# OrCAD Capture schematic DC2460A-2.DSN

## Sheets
1 LTC5566 - PAGE2: size Custom; title: DUAL PROGRAMMABLE GAIN MIXER; rev: 2; company: TM
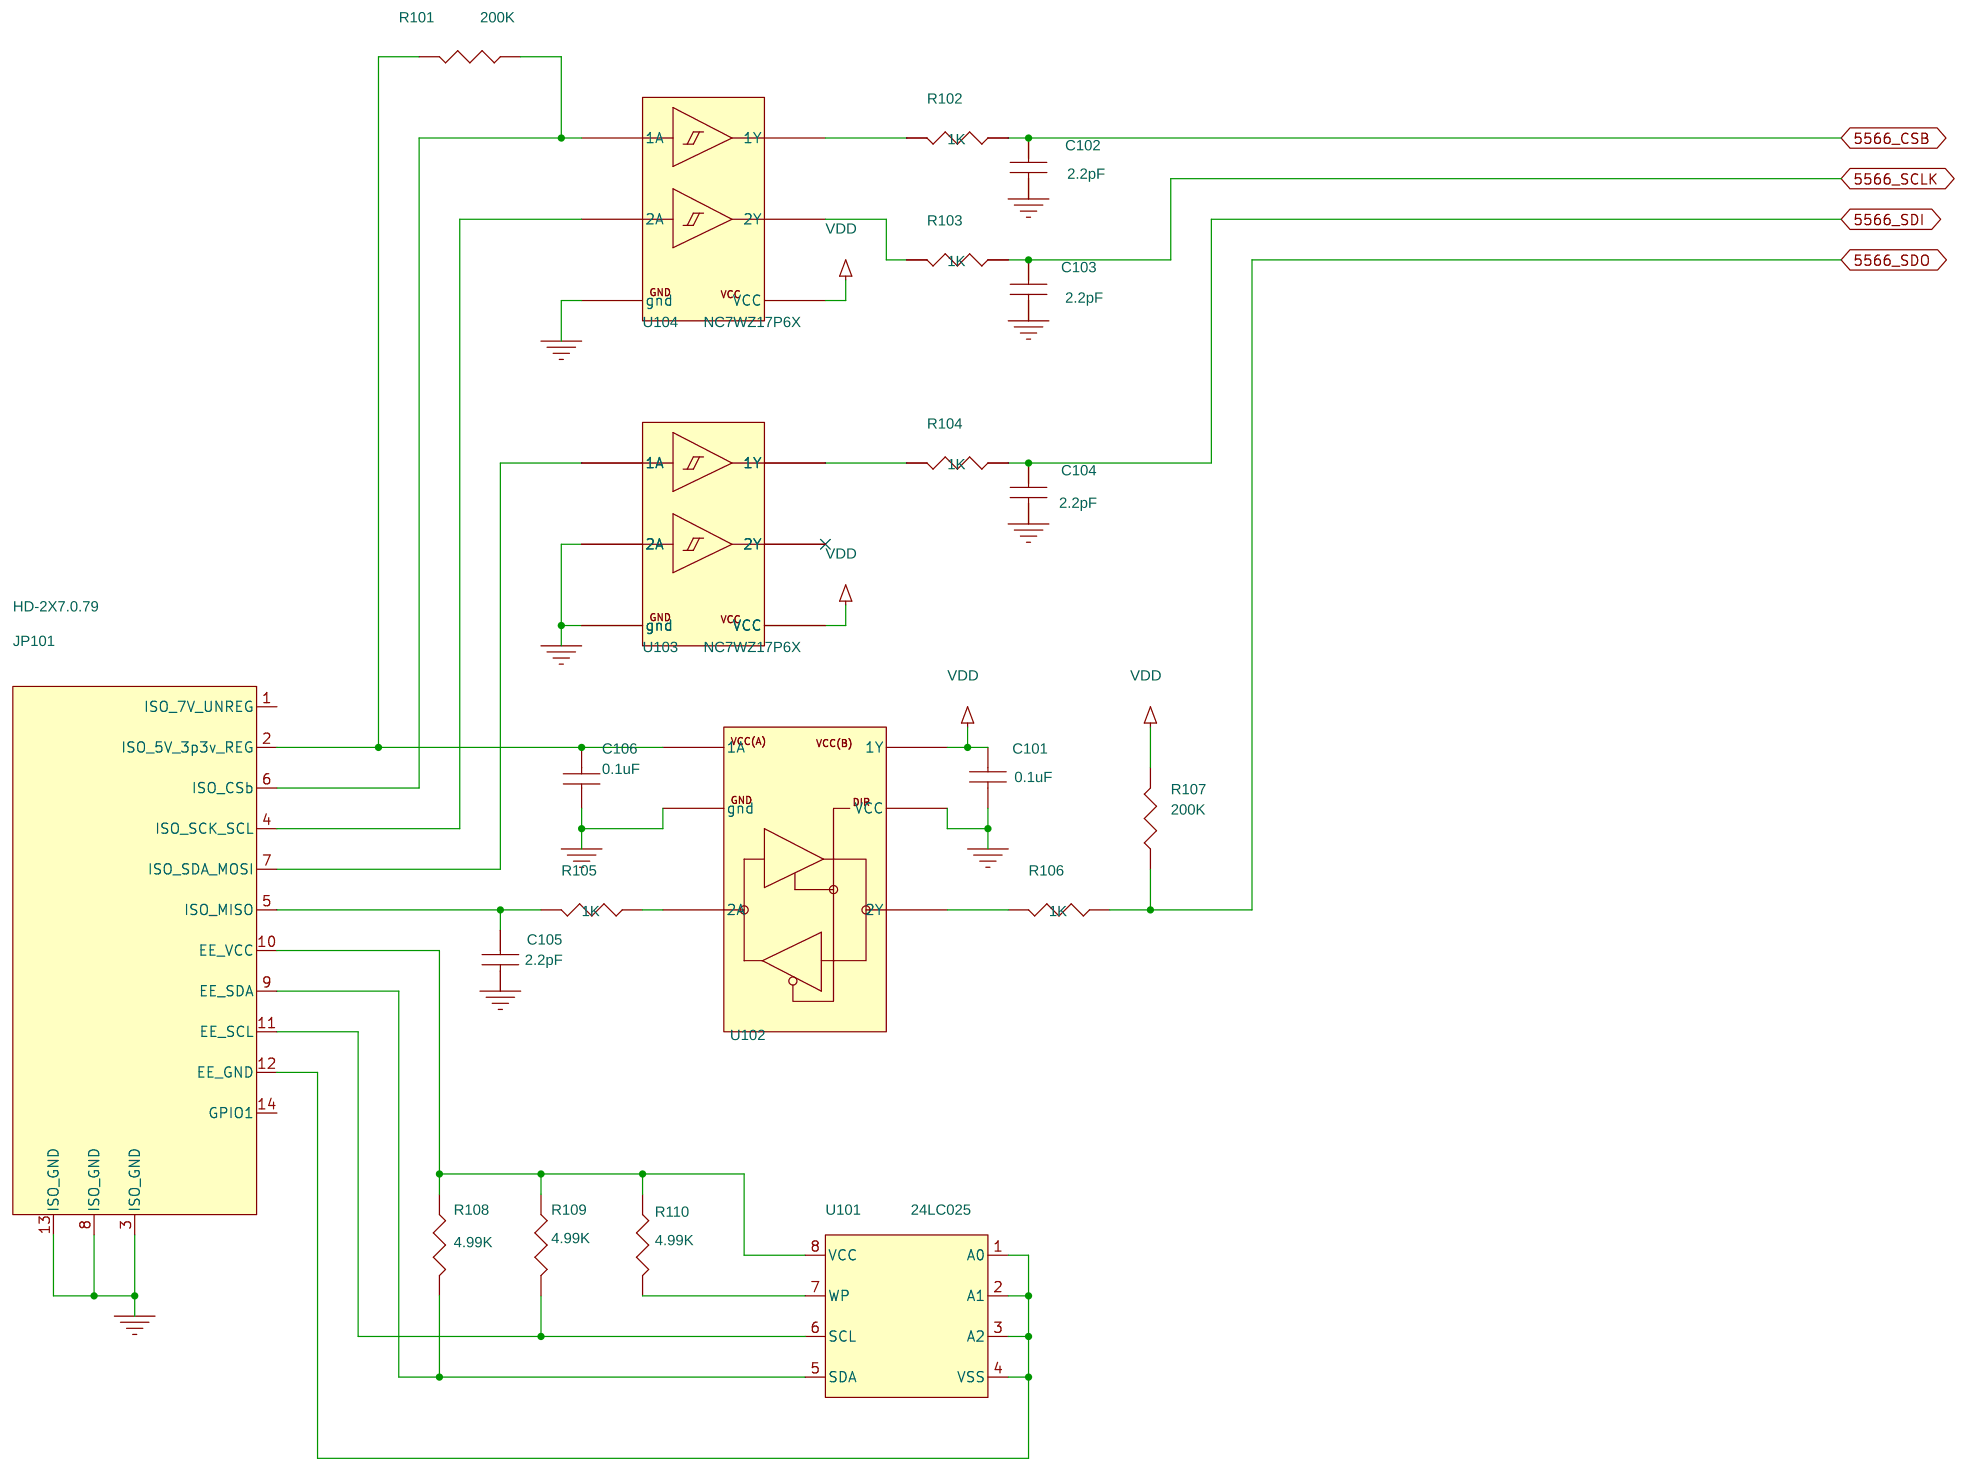
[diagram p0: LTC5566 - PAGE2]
2 LTC5566 - PAGE 1: size Custom
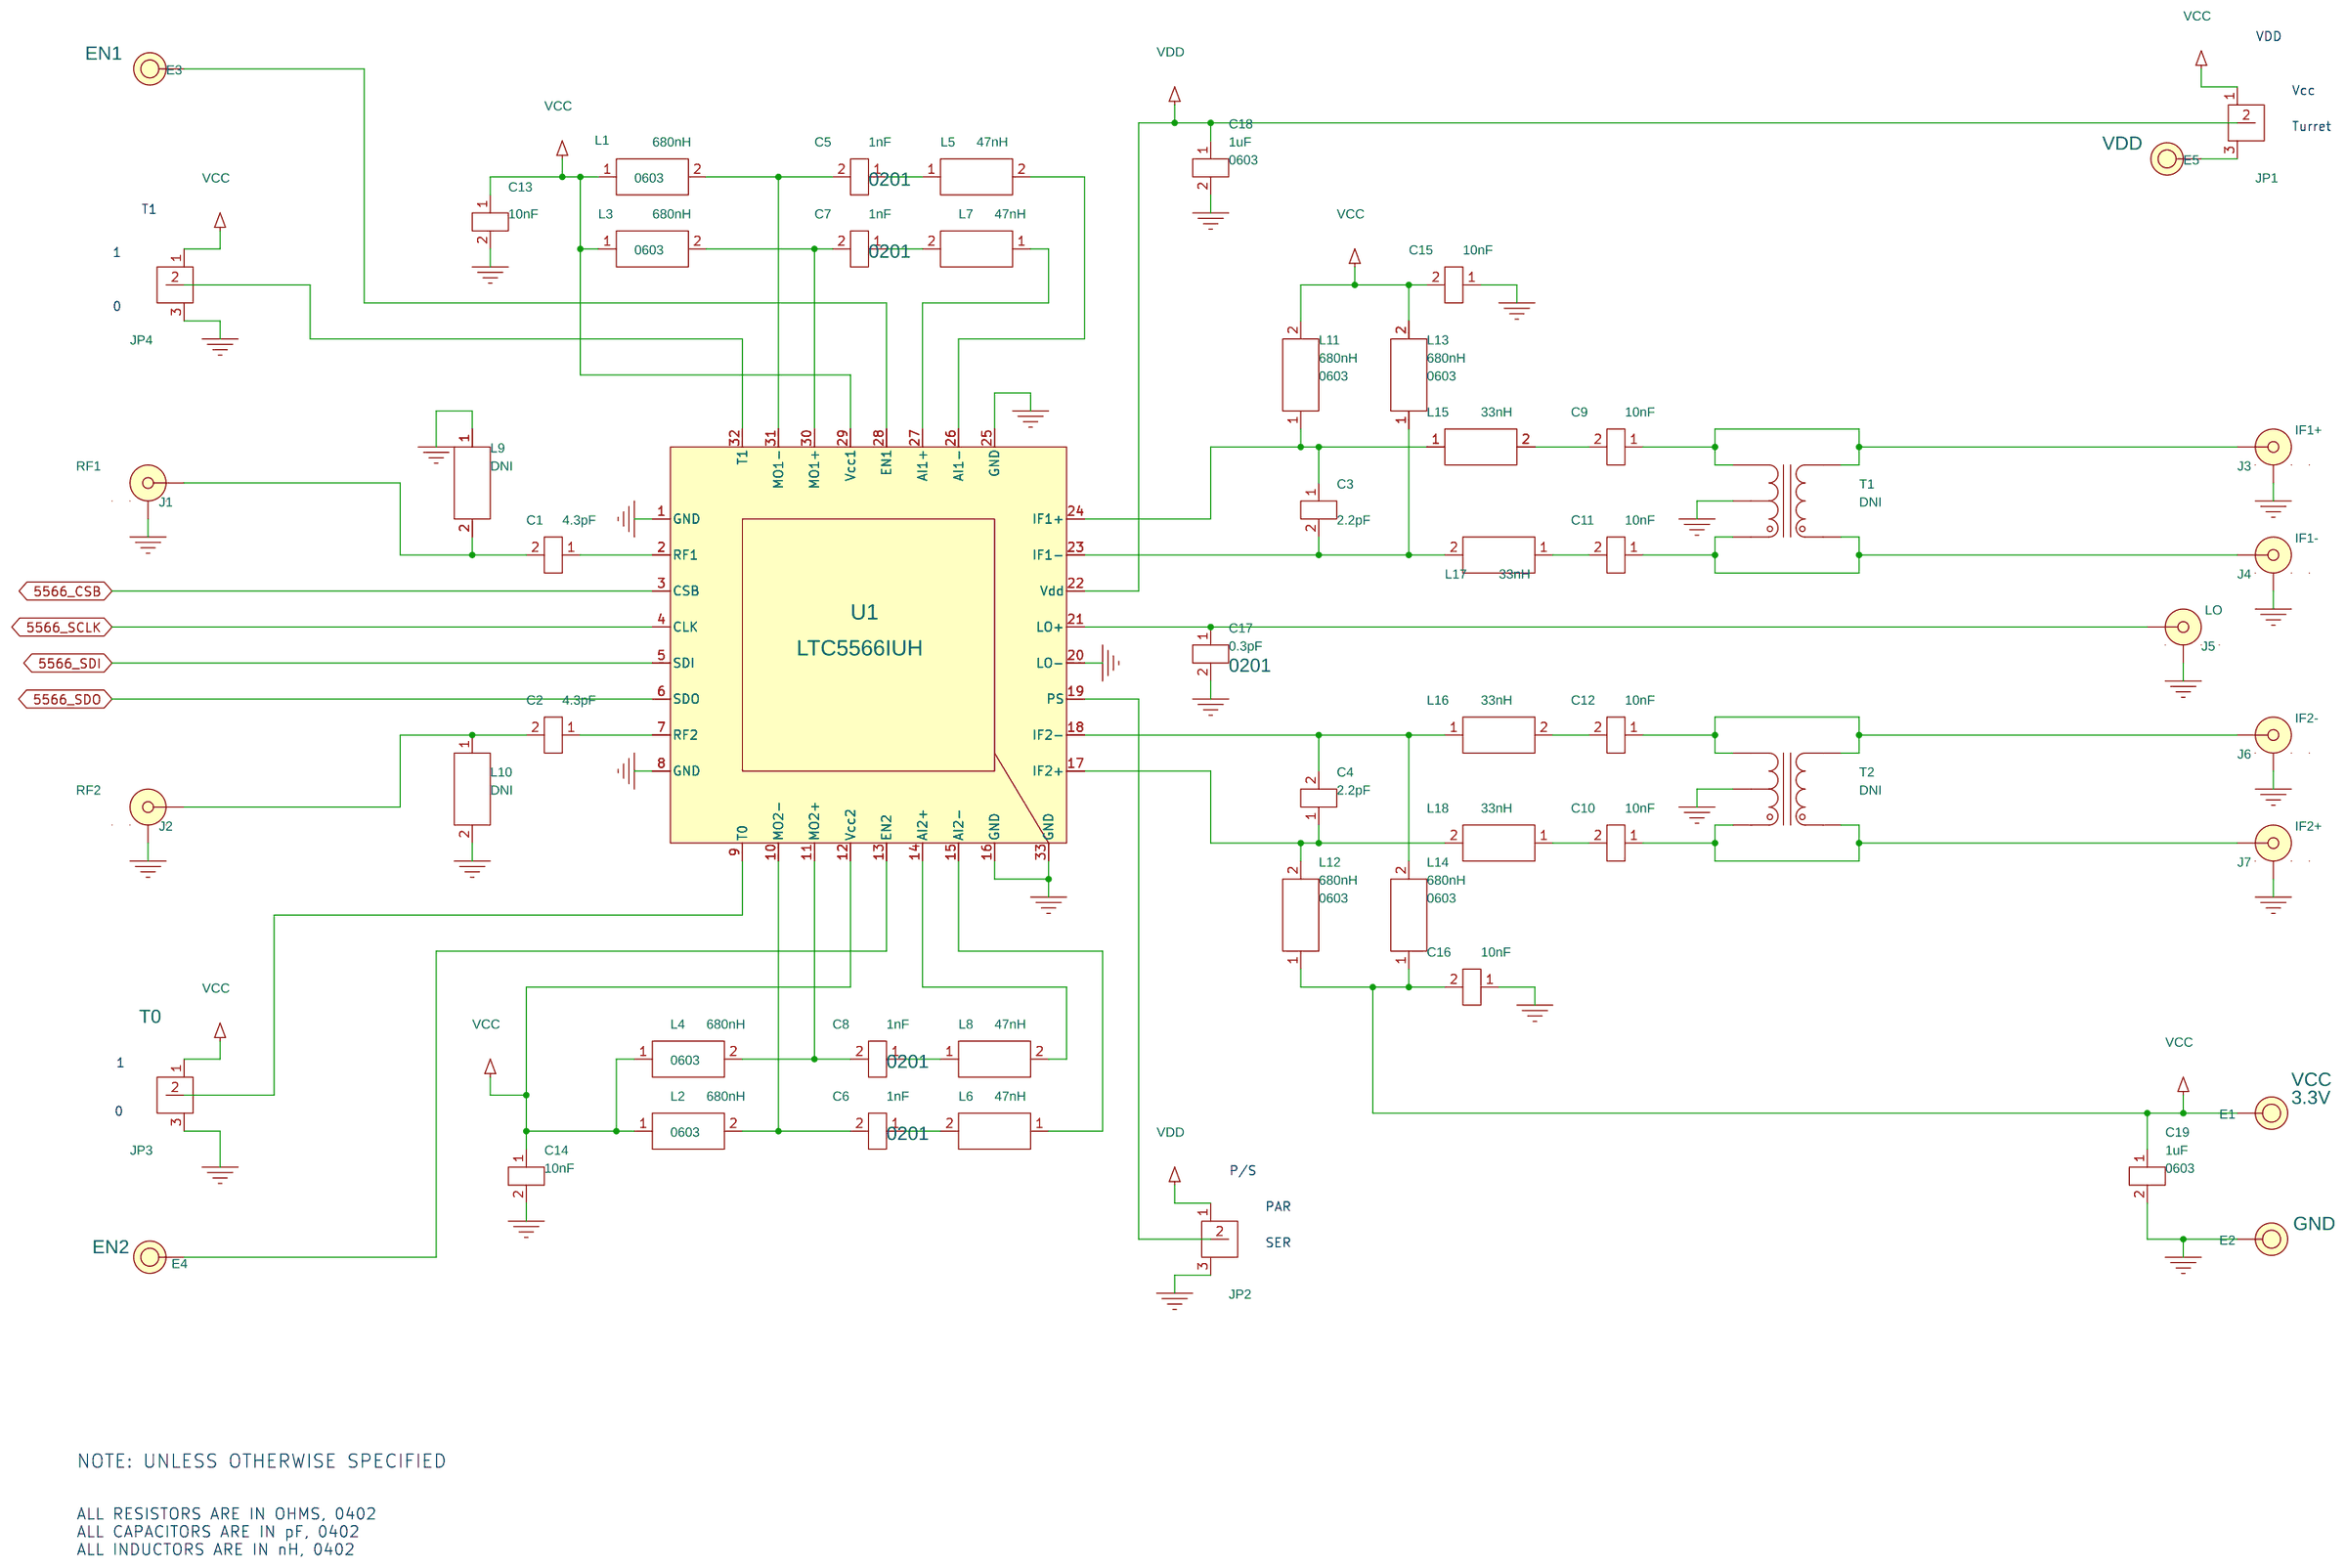
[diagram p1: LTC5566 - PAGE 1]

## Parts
sheet LTC5566 - PAGE2
C101  0.1uF  [0402]
C102  2.2pF  [0402]
C103  2.2pF  [0402]
C104  2.2pF  [0402]
C105  2.2pF  [0402]
C106  0.1uF  [0402]
JP101  HD-2X7.0.79  [HD2X7-079-MOLEX]
R101  200K  [0402]
R102  1K  [0402]
R103  1K  [0402]
R104  1K  [0402]
R105  1K  [0402]
R106  1K  [0402]
R107  200K  [0402]
R108  4.99K  [0402]
R109  4.99K  [0402]
R110  4.99K  [0402]
U101  24LC025  [ST-4.4MMTSSOP]
U102  Dual Transceiver  [SOT363(SC88)]
U103  Dual Buffer  [SC-70(6LEADS)\VISHAY]
U104  Dual Buffer  [SC-70(6LEADS)\VISHAY]
sheet LTC5566 - PAGE 1
C1  4.3pF  [0402_(1005)]
C2  4.3pF  [0402_(1005)]
C3  2.2pF  [0402_(1005)]
C4  2.2pF  [0402_(1005)]
C5  1nF  [0201]
C6  1nF  [0201]
C7  1nF  [0201]
C8  1nF  [0201]
C9  10nF  [0402_(1005)]
C10  10nF  [0402_(1005)]
C11  10nF  [0402_(1005)]
C12  10nF  [0402_(1005)]
C13  10nF  [0402_(1005)]
C14  10nF  [0402_(1005)]
C15  10nF  [0402_(1005)]
C16  10nF  [0402_(1005)]
C17  0.3pF  [0201]
C18  1uF  [0603]
C19  1uF  [0603]
E1  VCC  [MILLMAX2308]
E2  GND  [MILLMAX2308]
E3  EN1  [MILLMAX2308]
E4  EN2  [MILLMAX2308]
E5  VDD  [MILLMAX2308]
J1  RF1  [CON\SMA-END]
J2  RF2  [CON\SMA-END]
J3  IF1+  [CON\SMA-END]
J4  IF1-  [CON\SMA-END]
J5  LO  [CON\SMA-END]
J6  IF2-  [CON\SMA-END]
J7  IF2+  [CON\SMA-END]
JP1  JUMPER3  [TMM-103-02-L-S]
JP2  JUMPER3  [TMM-103-02-L-S]
JP3  JUMPER3  [TMM-103-02-L-S]
JP4  JUMPER3  [TMM-103-02-L-S]
L1  680nH  [0603]
L2  680nH  [0603]
L3  680nH  [0603]
L4  680nH  [0603]
L5  47nH  [0402_(1005)]
L6  47nH  [0402_(1005)]
L7  47nH  [0402_(1005)]
L8  47nH  [0402_(1005)]
L9  DNI  [0402_(1005)]
L10  DNI  [0402_(1005)]
L11  680nH  [0603]
L12  680nH  [0603]
L13  680nH  [0603]
L14  680nH  [0603]
L15  33nH  [0402_(1005)]
L16  33nH  [0402_(1005)]
L17  33nH  [0402_(1005)]
L18  33nH  [0402_(1005)]
T1  DNI  [TRANS-RF-TC4-1W-7ALN]
T2  DNI  [TRANS-RF-TC4-1W-7ALN]
U1  LTC5566IUH  [QFN-UH-32-5X5]

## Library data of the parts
C101 C106 = 0402ZD104KAT2A
C102-C105 = CAP_NP: CAP, 0603, 1uF, 10%, 10V, X5R; Part Number: AVX 0603ZD105KAT
JP101 = CONN.,_JTAG,_2X5,_0_0.100
R101 = CRCW0402200KJNED
R102-R110 = R_1: 0603: 0603; 1%: 1%
U101 = 24LC025_0
U102 = 74LVC1T45GW_SGL_PAK_0
U103 U104 = NC7WZ17P6X_SGL_PAK_0: 5th Part Field: NC7WZ17P6X
C1-C4 C9-C16 = DNI_0
C5-C8 C17 = DNI_0: Part Type: 0201_(603)
C18 C19 = DNI
E1 = Small_Turret: VOLTAGE: 3.3V
E2-E5 = Small_Turret
J1-J7 = CON_SMA-END_3: CONN, BNC, SMA 50-OHM EDGE-LANCH; 1 FILD: 50 Ohm; 2 FILD: 30MHz-3000MHz; Part Number: E.F.JOHNSON, 142-0701-851
JP1 JP4 = 3_PIN_2MM_JUMPER_-_DEMO
JP2 = 3_PIN_2MM_JUMPER_-_DEMO_0
JP3 = 3_PIN_2MM_JUMPER_-_DEMO: 1: T0
L1-L18 = 1_0.0NH_5%_0402
T1 T2 = TRANS-WBC-B
U1 = LTC5566_1

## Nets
GND: C13.2 C14.2 C15.1 C16.1 C17.2 C18.2 C19.2 C101.2 C102.2 C103.2 C104.2 C105.2 C106.1 E2.1 J1.2(GND) J1.3(GND) J1.4(GND) J1.5(GND) J2.2(GND) J2.3(GND) J2.4(GND) J2.5(GND) J3.2(GND) J3.3(GND) J3.4(GND) J3.5(GND) J4.2(GND) J4.3(GND) J4.4(GND) J4.5(GND) J5.2(GND) J5.3(GND) J5.4(GND) J5.5(GND) J6.2(GND) J6.3(GND) J6.4(GND) J6.5(GND) J7.2(GND) J7.3(GND) J7.4(GND) J7.5(GND) JP2.3 JP3.3 JP4.3 JP101.3(ISO_GND) JP101.8(ISO_GND) JP101.13(ISO_GND) L9.1 L10.2 T1.2 T2.2 U1.1(GND) U1.8(GND) U1.16(GND) U1.20(LO-) U1.25(GND) U1.33(GND) U102.2(gnd) U102.5(VCC) U103.2(gnd) U103.3(2A) U104.2(gnd)
VCC: C13.1 C14.1 C15.2 C16.2 C19.1 E1.1 JP1.1 JP3.1 JP4.1 L1.1 L2.1 L3.1 L4.1 L11.2 L12.1 L13.2 L14.1 U1.12(Vcc2) U1.29(Vcc1)
VDD: C18.1 C101.1 JP1.2 JP2.1 R107.1 U1.22(Vdd) U102.6(1Y) U103.5(VCC) U104.5(VCC)
5566_CSB: C102.1 R102.2 U1.3(CSB)
5566_SCLK: C103.1 R103.2 U1.4(CLK)
5566_SDI: C104.1 R104.2 U1.5(SDI)
5566_SDO: R106.2 R107.2 U1.6(SDO)
N40713: JP3.2 U1.9(T0)
N40741: JP4.2 U1.32(T1)
N40757: C17.1 J5.1(CENTER) U1.21(LO+)
N40785: C1.1 U1.2(RF1)
N40789: C2.1 U1.7(RF2)
N40837: C11.1 J4.1(CENTER) T1.1 T1.6
N40897: C4.2 L14.2 L16.1 U1.18(IF2-)
N40905: C4.1 L12.2 L18.2 U1.17(IF2+)
N40921: L8.2 U1.14(AI2+)
N40937: L6.1 U1.15(AI2-)
N41001: C3.1 L11.1 L15.1 U1.24(IF1+)
N41009: C3.2 L13.1 L17.2 U1.23(IF1-)
N41021: JP2.2 U1.19(PS)
N41085: C2.2 J2.1(CENTER) L10.1
N41089: C1.2 J1.1(CENTER) L9.2
N41133: C10.2 L18.1
N41137: C12.2 L16.2
N41145: C9.2 L15.2
N41321: E3.1 U1.28(EN1)
N41361: E4.1 U1.13(EN2)
N69900: C6.2 L2.2 U1.10(MO2-)
N69932: C8.2 L4.2 U1.11(MO2+)
N73620: C7.1 L7.2
N73624: C5.1 L5.1
N76667: L5.2 U1.26(AI1-)
N76702: C7.2 L3.2 U1.30(MO1+)
N76710: L7.1 U1.27(AI1+)
N78123: C5.2 L1.2 U1.31(MO1-)
N84915: C6.1 L6.2
N84921: C8.1 L8.1
N130472: C11.2 L17.1
N194638: E5.1 JP1.3
N240202: JP101.11(EE_SCL) R109.1 U101.6(SCL)
N240206: C105.1 JP101.5(ISO_MISO) R105.1
N240210: JP101.7(ISO_SDA_MOSI) U103.1(1A)
N240214: JP101.9(EE_SDA) R108.1 U101.5(SDA)
N240218: JP101.10(EE_VCC) R108.2 R109.2 R110.2 U101.8(VCC)
N240222: JP101.4(ISO_SCK_SCL) U104.3(2A)
N240226: JP101.6(ISO_CSb) R101.2 U104.1(1A)
N240242: R110.1 U101.7(WP)
N240270: JP101.12(EE_GND) U101.1(A0) U101.2(A1) U101.3(A2) U101.4(VSS)
N240314: R103.1 U104.4(2Y)
N240318: C106.2 JP101.2(ISO_5V_3p3v_REG) R101.1 U102.1(1A)
N240462: R105.2 U102.3(2A)
N240766: R106.1 U102.4(2Y)
N240882: R104.1 U103.6(1Y)
N241050: R102.1 U104.6(1Y)
N16714792: C9.1 J3.1(CENTER) T1.3 T1.4
N16715764: C10.1 J7.1(CENTER) T2.1 T2.6
N16715810: C12.1 J6.1(CENTER) T2.3 T2.4

Not connected (* = marked no-connect by the designer): JP101 1(ISO_7V_UNREG) 14(GPIO1); U103 4(2Y)*

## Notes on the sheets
sheet 2
- VDD
- Vcc
- Turret
- T1
- 1
- 0
- 1
- 0
- P/S
- PAR
- SER
- NOTE: UNLESS OTHERWISE SPECIFIED
- ALL RESISTORS ARE IN OHMS, 0402
  ALL CAPACITORS ARE IN pF, 0402
  ALL INDUCTORS ARE IN nH, 0402
